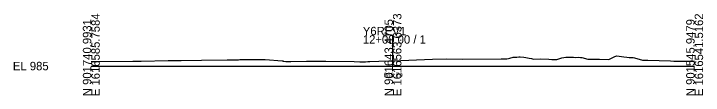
# Model space of a CAD drawing. Extents: x -26 to 203, y -10 to 2517.
# Drawn here: x -25.7 to 202.8, y 1990.3 to 2017.4 of the extents above; entities that cross this region are included whole.
import ezdxf

# ---------------------------------------------------------------- set-up
doc = ezdxf.new("R2010")
doc.units = 0
for name, color, linetype in [('Exist Cross Section Cell', 7, 'Continuous'), ('Exist XS Center Line Elevation Label', 7, 'Continuous'), ('Exist XS Ground Line', 7, 'Continuous')]:
    doc.layers.add(name, color=color, linetype=linetype)

msp = doc.modelspace()

# ---------------------------------------------------------------- linework, layer by layer
at = {"layer": 'Exist Cross Section Cell'}
for p, q in [((100, 2000), (100, 2010.23)), ((0, 2000), (100, 2000)), ((100, 2000), (200, 2000))]:
    msp.add_line(p, q, dxfattribs=at)
at = {"layer": 'Exist XS Ground Line'}
msp.add_lwpolyline([(0, 2001.47), (1.65, 2001.5), (2.02, 2001.51), (13.75, 2001.64), (14.5, 2001.65), (14.91, 2001.65), (16.57, 2001.68), (25.47, 2001.8), (29.83, 2001.86), (36.54, 2001.95), (45.07, 2002.09), (46.68, 2002.09), (48.45, 2002.11), (48.78, 2002.11), (49.22, 2002.13), (57.23, 2002.17), (57.58, 2002.16), (63.24, 2001.77), (63.61, 2001.75), (63.63, 2001.64), (64.49, 2001.51), (64.82, 2001.51), (66.11, 2001.53), (71.34, 2001.58), (77.78, 2001.65), (87.13, 2001.48), (89.04, 2001.42), (90.29, 2001.38), (90.9, 2001.36), (91.62, 2001.53), (92.37, 2001.55), (95.28, 2001.67), (98.65, 2001.74), (100, 2001.79), (113.11, 2002.32), (117.76, 2002.36), (123.03, 2002.33), (135.91, 2002.35), (137.73, 2002.37), (138.29, 2002.54), (138.73, 2002.66), (139.81, 2002.92), (141.09, 2003), (141.69, 2003.06), (142.13, 2003.05), (143.4, 2002.95), (144.03, 2002.88), (145.19, 2002.65), (145.95, 2002.5), (146.57, 2002.34), (149.06, 2002.35), (151.62, 2002.27), (152.68, 2002.2), (154.32, 2002.16), (155.92, 2002.68), (157.34, 2002.99), (157.92, 2002.98), (159.79, 2002.9), (160.4, 2002.88), (161.66, 2002.92), (162.15, 2002.87), (162.62, 2002.82), (164.58, 2002.27), (168.46, 2002.26), (171.56, 2002.22), (173.35, 2003.09), (174.09, 2003.41), (174.97, 2003.27), (175.71, 2003.2), (176.58, 2003.03), (177.49, 2002.99), (178.33, 2002.88), (179.64, 2002.83), (180.08, 2002.68), (182.67, 2001.97), (184.04, 2002.01), (184.51, 2001.97), (192.02, 2001.78), (193.15, 2001.64), (199.23, 2001.59), (200, 2001.64)], dxfattribs=at)

# ---------------------------------------------------------------- texts
at = {"layer": 'Exist Cross Section Cell'}
for s, p in [('E 1616585.7584', (2.8, 1990)), ('E 1616563.6373', (102.8, 1990)), ('E 1616541.5162', (202.8, 1990)), ('N 901740.9931', (0, 1990)), ('N 901643.4705', (100, 1990)), ('N 901545.9479', (200, 1990))]:
    msp.add_text(s, height=2.8, rotation=90, dxfattribs=at).set_placement(p)
for s, p in [('Y6REV1', (90, 2010.23)), ('12+00.00 / 1', (90, 2007.43)), ('EL 985', (-26, 1998.6))]:
    msp.add_text(s, height=2.8, dxfattribs=at).set_placement(p)
at = {"layer": 'Exist XS Center Line Elevation Label'}
msp.add_text('986.79', height=1.5, dxfattribs=at).set_placement((96.89, 1996.29))
msp.add_text('986.79', height=1.5, dxfattribs=at).set_placement((96.89, 1996.29))

doc.saveas('drawing.dxf')
